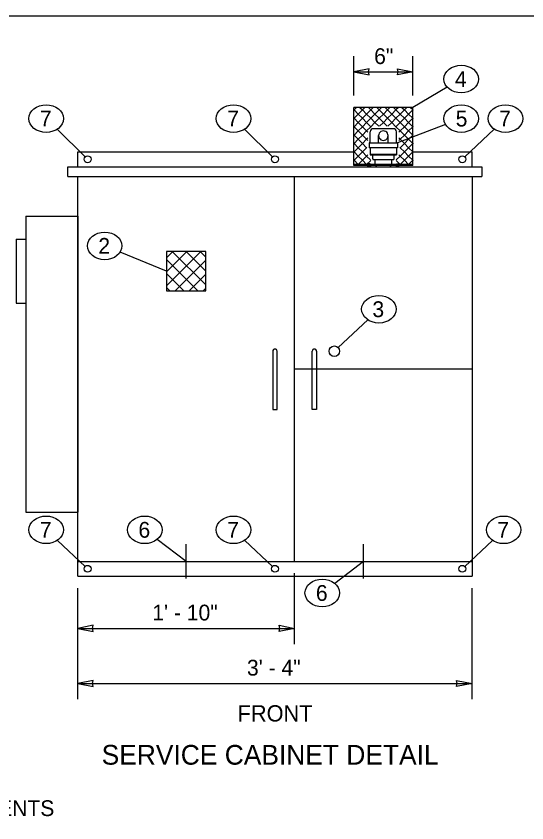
# Model space of a CAD drawing. Extents: x 99862 to 103680, y 99470 to 105076.
# Drawn here: x 100524 to 101043, y 101258 to 102076 of the extents above; entities that cross this region are included whole.
import ezdxf

# ---------------------------------------------------------------- set-up
doc = ezdxf.new("R2010")
doc.units = 0
for name, color, linetype in [('Level 1', 7, 'Continuous'), ('Level 15', 7, 'Continuous'), ('Level 20', 7, 'Continuous'), ('Level 35', 7, 'Continuous'), ('Level 40', 7, 'Continuous')]:
    doc.layers.add(name, color=color, linetype=linetype)

msp = doc.modelspace()

# ---------------------------------------------------------------- linework, layer by layer
at = {"layer": 'Level 1'}
for p, q in [((100866.96, 101925.19), (100866.96, 101982.94)), ((100926.96, 101982.94), (100866.96, 101982.94)), ((100866.96, 101980.71), (100867.18, 101980.49)), ((100867.18, 101980.49), (100866.96, 101980.27)), ((100867.18, 101980.49), (100869.64, 101982.94)), ((100871.44, 101976.24), (100867.18, 101980.49)), ((100875.69, 101980.49), (100871.44, 101976.24)), ((100873.24, 101982.94), (100875.69, 101980.49)), ((100878.14, 101982.94), (100875.69, 101980.49)), ((100875.69, 101980.49), (100879.95, 101976.24)), ((100879.95, 101976.24), (100884.2, 101980.49)), ((100884.2, 101980.49), (100881.75, 101982.94)), ((100886.65, 101982.94), (100884.2, 101980.49)), ((100884.2, 101980.49), (100888.45, 101976.24)), ((100888.45, 101976.24), (100892.71, 101980.49)), ((100892.71, 101980.49), (100890.26, 101982.94)), ((100895.16, 101982.94), (100892.71, 101980.49)), ((100892.71, 101980.49), (100896.96, 101976.24)), ((100896.96, 101976.24), (100901.22, 101980.49)), ((100901.22, 101980.49), (100898.76, 101982.94)), ((100903.67, 101982.94), (100901.22, 101980.49)), ((100901.22, 101980.49), (100905.47, 101976.24)), ((100905.47, 101976.24), (100909.73, 101980.49)), ((100909.73, 101980.49), (100907.27, 101982.94)), ((100912.18, 101982.94), (100909.73, 101980.49)), ((100909.73, 101980.49), (100913.98, 101976.24)), ((100913.98, 101976.24), (100918.23, 101980.49)), ((100915.78, 101982.94), (100918.23, 101980.49)), ((100918.23, 101980.49), (100920.69, 101982.94)), ((100918.23, 101980.49), (100922.49, 101976.24)), ((100922.49, 101976.24), (100926.74, 101980.49)), ((100926.74, 101980.49), (100924.29, 101982.94)), ((100926.96, 101980.71), (100926.74, 101980.49)), ((100926.74, 101980.49), (100926.96, 101980.27)), ((100926.96, 101925.19), (100926.96, 101982.95)), ((100866.96, 101972.21), (100867.18, 101971.98)), ((100867.18, 101971.98), (100866.96, 101971.76)), ((100867.18, 101971.98), (100871.44, 101976.24)), ((100871.44, 101967.73), (100867.18, 101971.98)), ((100871.44, 101976.24), (100875.69, 101971.98)), ((100875.69, 101971.98), (100871.44, 101967.73)), ((100879.95, 101976.24), (100875.69, 101971.98)), ((100875.69, 101971.98), (100879.95, 101967.73)), ((100884.2, 101971.98), (100879.95, 101976.24)), ((100879.95, 101967.73), (100884.2, 101971.98)), ((100888.45, 101976.24), (100884.2, 101971.98)), ((100884.2, 101971.98), (100888.45, 101967.73)), ((100892.71, 101971.98), (100888.45, 101976.24)), ((100888.45, 101967.73), (100892.71, 101971.98)), ((100896.96, 101976.24), (100892.71, 101971.98)), ((100892.71, 101971.98), (100896.96, 101967.73)), ((100901.22, 101971.98), (100896.96, 101976.24)), ((100896.96, 101967.73), (100901.22, 101971.98)), ((100905.47, 101976.24), (100901.22, 101971.98)), ((100901.22, 101971.98), (100905.47, 101967.73)), ((100909.73, 101971.98), (100905.47, 101976.24)), ((100905.47, 101967.73), (100909.73, 101971.98)), ((100913.98, 101976.24), (100909.73, 101971.98)), ((100909.73, 101971.98), (100913.98, 101967.73)), ((100918.23, 101971.98), (100913.98, 101976.24)), ((100913.98, 101967.73), (100918.23, 101971.98)), ((100922.49, 101976.24), (100918.23, 101971.98)), ((100918.23, 101971.98), (100922.49, 101967.73)), ((100926.74, 101971.98), (100922.49, 101976.24)), ((100922.49, 101967.73), (100926.74, 101971.98)), ((100926.96, 101972.2), (100926.74, 101971.98)), ((100926.74, 101971.98), (100926.96, 101971.76)), ((100866.96, 101963.7), (100867.18, 101963.48)), ((100867.18, 101963.48), (100866.96, 101963.25)), ((100867.18, 101963.48), (100871.44, 101967.73)), ((100871.44, 101959.22), (100867.18, 101963.48)), ((100871.44, 101967.73), (100875.69, 101963.48)), ((100875.69, 101963.48), (100871.44, 101959.22)), ((100879.95, 101967.73), (100875.69, 101963.48)), ((100875.69, 101963.48), (100879.95, 101959.22)), ((100884.2, 101963.48), (100879.95, 101967.73)), ((100879.95, 101959.22), (100884.2, 101963.48)), ((100888.45, 101967.73), (100884.2, 101963.48)), ((100884.2, 101963.48), (100884.42, 101963.26)), ((100892.33, 101963.86), (100888.45, 101967.73)), ((100896.96, 101967.73), (100893.09, 101963.86)), ((100900.84, 101963.86), (100896.96, 101967.73)), ((100905.47, 101967.73), (100901.6, 101963.86)), ((100909.73, 101963.48), (100905.47, 101967.73)), ((100909.51, 101963.26), (100909.73, 101963.48)), ((100913.98, 101967.73), (100909.73, 101963.48)), ((100909.73, 101963.48), (100913.98, 101959.22)), ((100918.23, 101963.48), (100913.98, 101967.73)), ((100913.98, 101959.22), (100918.23, 101963.48)), ((100922.49, 101967.73), (100918.23, 101963.48)), ((100918.23, 101963.48), (100922.49, 101959.22)), ((100926.74, 101963.48), (100922.49, 101967.73)), ((100922.49, 101959.22), (100926.74, 101963.48)), ((100926.96, 101963.7), (100926.74, 101963.48)), ((100926.74, 101963.48), (100926.96, 101963.26)), ((100866.96, 101955.19), (100867.18, 101954.97)), ((100867.18, 101954.97), (100866.96, 101954.75)), ((100867.18, 101954.97), (100871.44, 101959.22)), ((100871.44, 101950.71), (100867.18, 101954.97)), ((100871.44, 101959.22), (100875.69, 101954.97)), ((100875.69, 101954.97), (100871.44, 101950.71)), ((100879.95, 101959.22), (100875.69, 101954.97)), ((100875.69, 101954.97), (100879.95, 101950.71)), ((100881.32, 101957.85), (100879.95, 101959.22)), ((100883.73, 101947.01), (100883.73, 101958.24)), ((100906.99, 101961.45), (100886.94, 101961.45)), ((100892.15, 101947.01), (100892.15, 101954.39)), ((100901.78, 101947.01), (100901.78, 101954.39)), ((100910.2, 101947.01), (100910.2, 101958.24)), ((100913.98, 101959.22), (100912.6, 101957.85)), ((100918.23, 101954.97), (100913.98, 101959.22)), ((100913.98, 101950.71), (100918.23, 101954.97)), ((100922.49, 101959.22), (100918.23, 101954.97)), ((100918.23, 101954.97), (100922.49, 101950.71)), ((100926.74, 101954.97), (100922.49, 101959.22)), ((100922.49, 101950.71), (100926.74, 101954.97)), ((100926.96, 101955.19), (100926.74, 101954.97)), ((100926.74, 101954.97), (100926.96, 101954.75)), ((100866.96, 101946.68), (100867.18, 101946.46)), ((100867.18, 101946.46), (100866.96, 101946.24)), ((100867.18, 101946.46), (100871.44, 101950.71)), ((100871.44, 101942.2), (100867.18, 101946.46)), ((100871.44, 101950.71), (100875.69, 101946.46)), ((100875.69, 101946.46), (100871.44, 101942.2)), ((100879.95, 101950.71), (100875.69, 101946.46)), ((100875.69, 101946.46), (100879.95, 101942.2)), ((100879.95, 101950.71), (100881.32, 101952.09)), ((100881.24, 101949.42), (100879.95, 101950.71)), ((100883.73, 101947.01), (100882.52, 101947.01)), ((100882.52, 101947.01), (100882.52, 101942.2)), ((100883.73, 101947.01), (100910.2, 101947.01)), ((100910.2, 101947.01), (100911.4, 101947.01)), ((100911.4, 101947.01), (100911.4, 101942.2)), ((100912.6, 101952.09), (100913.98, 101950.71)), ((100913.98, 101950.71), (100912.68, 101949.42)), ((100918.23, 101946.46), (100913.98, 101950.71)), ((100913.98, 101942.2), (100918.23, 101946.46)), ((100922.49, 101950.71), (100918.23, 101946.46)), ((100918.23, 101946.46), (100922.49, 101942.2)), ((100926.74, 101946.46), (100922.49, 101950.71)), ((100922.49, 101942.2), (100926.74, 101946.46)), ((100926.96, 101946.68), (100926.74, 101946.46)), ((100926.74, 101946.46), (100926.96, 101946.24)), ((100866.96, 101938.17), (100867.18, 101937.95)), ((100867.18, 101937.95), (100866.96, 101937.73)), ((100867.18, 101937.95), (100871.44, 101942.2)), ((100871.44, 101933.7), (100867.18, 101937.95)), ((100871.44, 101942.2), (100875.69, 101937.95)), ((100875.69, 101937.95), (100871.44, 101933.7)), ((100879.95, 101942.2), (100875.69, 101937.95)), ((100875.69, 101937.95), (100879.95, 101933.7)), ((100879.95, 101942.2), (100880.12, 101942.38)), ((100880.12, 101942.03), (100879.95, 101942.2)), ((100911.4, 101942.2), (100882.52, 101942.2)), ((100883.73, 101942.2), (100883.73, 101934.98)), ((100910.2, 101942.2), (100910.2, 101934.98)), ((100913.81, 101942.38), (100913.98, 101942.2)), ((100913.98, 101942.2), (100913.81, 101942.03)), ((100918.23, 101937.95), (100913.98, 101942.2)), ((100913.98, 101933.7), (100918.23, 101937.95)), ((100922.49, 101942.2), (100918.23, 101937.95)), ((100918.23, 101937.95), (100922.49, 101933.7)), ((100926.74, 101937.95), (100922.49, 101942.2)), ((100922.49, 101933.7), (100926.74, 101937.95)), ((100926.96, 101938.17), (100926.74, 101937.95)), ((100926.74, 101937.95), (100926.96, 101937.73)), ((100866.96, 101929.66), (100867.18, 101929.44)), ((100867.18, 101929.44), (100871.44, 101933.7)), ((100871.44, 101933.7), (100875.69, 101929.44)), ((100879.95, 101933.7), (100875.69, 101929.44)), ((100879.95, 101933.7), (100881.32, 101935.07)), ((100883.91, 101929.73), (100879.95, 101933.7)), ((100883.73, 101935.58), (100910.2, 101935.58)), ((100883.73, 101934.98), (100910.2, 101934.98)), ((100886.13, 101930.77), (100886.13, 101934.98)), ((100886.73, 101930.16), (100907.19, 101930.16)), ((100888.54, 101925.35), (100888.54, 101930.16)), ((100905.39, 101925.35), (100905.39, 101930.16)), ((100907.79, 101930.77), (100907.79, 101934.98)), ((100913.98, 101933.7), (100910.01, 101929.73)), ((100912.6, 101935.07), (100913.98, 101933.7)), ((100918.23, 101929.44), (100913.98, 101933.7)), ((100922.49, 101933.7), (100918.23, 101929.44)), ((100926.74, 101929.44), (100922.49, 101933.7)), ((100926.96, 101929.66), (100926.74, 101929.44)), ((100867.18, 101929.44), (100866.96, 101929.22)), ((100926.96, 101925.19), (100866.96, 101925.19)), ((100866.96, 101924.15), (100866.96, 101925.09)), ((100926.96, 101925.09), (100866.96, 101925.09)), ((100926.96, 101924.15), (100866.96, 101924.15)), ((100871.44, 101925.19), (100867.18, 101929.44)), ((100875.69, 101929.44), (100871.44, 101925.19)), ((100875.69, 101929.44), (100879.95, 101925.19)), ((100879.95, 101925.19), (100884.09, 101929.33)), ((100890.95, 101922.94), (100902.98, 101922.94)), ((100909.83, 101929.33), (100913.98, 101925.19)), ((100913.98, 101925.19), (100918.23, 101929.44)), ((100918.23, 101929.44), (100922.49, 101925.19)), ((100922.49, 101925.19), (100926.74, 101929.44)), ((100926.74, 101929.44), (100926.96, 101929.22)), ((100926.96, 101924.15), (100926.96, 101925.09)), ((100534.46, 101872.94), (100586.96, 101872.94)), ((100534.46, 101872.94), (100534.46, 101572.94)), ((100586.96, 101872.94), (100586.96, 101572.94)), ((100524.46, 101849.63), (100534.46, 101849.63)), ((100524.46, 101849.63), (100524.46, 101784.63)), ((100524.46, 101784.63), (100534.46, 101784.63)), ((100784.75, 101735.95), (100784.75, 101732.99)), ((100789.18, 101732.99), (100789.18, 101735.95)), ((100824.75, 101732.99), (100824.75, 101735.95)), ((100829.18, 101735.95), (100829.18, 101732.99)), ((100784.75, 101732.99), (100784.75, 101676.86)), ((100789.18, 101676.86), (100789.18, 101732.99)), ((100824.75, 101676.86), (100824.75, 101732.99)), ((100829.18, 101732.99), (100829.18, 101676.86)), ((100784.75, 101676.86), (100789.18, 101676.86)), ((100829.18, 101676.86), (100824.75, 101676.86)), ((100534.46, 101572.94), (100586.96, 101572.94))]:
    msp.add_line(p, q, dxfattribs=at)
msp.add_lwpolyline([(99862, 99999.5), (103151, 99999.5), (103151, 102075.5), (99862, 102075.5)], close=True, dxfattribs=at)
msp.add_circle((100847.27, 101735.95), 5.34, dxfattribs=at)
for centre, radius, start, end in [((100886.94, 101958.24), 3.21, 90, 180), ((100896.96, 101954.39), 4.81, 359.99971, 180), ((100896.96, 101954.39), 4.81, 180, 0.00029), ((100906.99, 101958.24), 3.21, 0, 90), ((100886.73, 101930.77), 0.602, 180, 270), ((100907.19, 101930.77), 0.602, 270, 0), ((100890.95, 101925.35), 2.41, 180, 270), ((100902.98, 101925.35), 2.41, 270, 0), ((100786.96, 101735.95), 2.22, 0, 180), ((100826.96, 101735.95), 2.22, 0, 180)]:
    msp.add_arc(centre, radius, start, end, dxfattribs=at)
at = {"layer": 'Level 15'}
for p, q in [((100866.96, 101994.94), (100866.96, 102034.94)), ((100926.96, 101994.94), (100926.96, 102034.94)), ((100866.96, 102018.94), (100926.96, 102018.94)), ((100961.82, 102003.41), (100926.96, 101982.94)), ((100960.14, 101965.65), (100911.4, 101947.01)), ((100594.47, 101932.9), (100566.01, 101960.84)), ((100784.47, 101932.9), (100756.01, 101960.84)), ((100979.51, 101932.84), (101009.48, 101961.03)), ((100576.96, 101922.94), (100996.96, 101922.94)), ((100576.96, 101912.94), (100576.96, 101922.94)), ((100996.96, 101922.94), (100996.96, 101912.94)), ((100576.96, 101912.94), (100996.96, 101912.94)), ((100676.96, 101817.13), (100629.9, 101836.33)), ((100851.12, 101739.65), (100881.09, 101767.83)), ((100594.41, 101517.84), (100566.3, 101544.28)), ((100696.96, 101522.94), (100667.63, 101545.29)), ((100696.96, 101505.44), (100696.96, 101540.44)), ((100784.41, 101517.84), (100756.3, 101544.28)), ((100876.96, 101505.44), (100876.96, 101540.44)), ((100979.51, 101517.84), (101007.62, 101544.28)), ((100876.96, 101522.94), (100847.63, 101500.6)), ((100806.96, 101439.08), (100806.96, 101510.94)), ((100586.96, 101383.22), (100586.96, 101495.94)), ((100986.96, 101383.22), (100986.96, 101495.94)), ((100586.96, 101455.08), (100806.96, 101455.08)), ((100586.96, 101399.22), (100986.96, 101399.22))]:
    msp.add_line(p, q, dxfattribs=at)
for points in [[(100866.96, 102018.94), (100882.69, 102015.86), (100881.96, 102018.94), (100882.69, 102022.03)], [(100926.96, 102018.94), (100911.24, 102015.86), (100911.97, 102018.94), (100911.24, 102022.03)], [(100586.96, 101455.08), (100602.69, 101452), (100601.96, 101455.08), (100602.69, 101458.17)], [(100806.96, 101455.08), (100791.24, 101452), (100791.97, 101455.08), (100791.24, 101458.17)], [(100586.96, 101399.22), (100602.69, 101396.14), (100601.96, 101399.22), (100602.69, 101402.31)], [(100986.96, 101399.22), (100971.24, 101396.14), (100971.97, 101399.22), (100971.24, 101402.31)]]:
    msp.add_lwpolyline(points, close=True, dxfattribs=at)
for centre in [(100596.96, 101930.44), (100786.96, 101930.44), (100976.96, 101930.44), (100596.96, 101515.44), (100786.96, 101515.44), (100976.96, 101515.44)]:
    msp.add_circle(centre, 3.5, dxfattribs=at)
at = {"layer": 'Level 20'}
for centre, major_axis in [((100975.93, 102011.69), (-17.5, 0)), ((100554.96, 101971.69), (-17.5, 0)), ((100744.96, 101971.69), (-17.5, 0)), ((100975.93, 101971.69), (-17.5, 0)), ((101020.82, 101971.69), (-17.5, 0)), ((100614.31, 101842.68), (-17.5, 0)), ((100892.43, 101778.5), (-17.5, 0)), ((100554.96, 101554.94), (-17.5, 0)), ((100654.96, 101554.94), (-17.5, 0)), ((100744.96, 101554.94), (-17.5, 0)), ((101018.96, 101554.94), (-17.5, 0)), ((100834.96, 101490.94), (17.5, 0))]:
    msp.add_ellipse(centre, major_axis=major_axis, ratio=0.8, dxfattribs=at)
at = {"layer": 'Level 35'}
msp.add_line((100806.96, 101717.94), (100986.96, 101717.94), dxfattribs=at)
at = {"layer": 'Level 40'}
for p, q in [((100586.96, 101937.94), (100866.96, 101937.94)), ((100586.96, 101922.94), (100586.96, 101937.94)), ((100926.96, 101937.94), (100986.96, 101937.94)), ((100986.96, 101922.94), (100986.96, 101937.94)), ((100586.96, 101922.94), (100986.96, 101922.94)), ((100586.96, 101507.94), (100586.96, 101912.94)), ((100806.96, 101522.94), (100806.96, 101912.94)), ((100986.96, 101912.94), (100986.96, 101507.94)), ((100676.96, 101802.33), (100711.76, 101837.13)), ((100676.96, 101816.47), (100697.62, 101837.13)), ((100676.96, 101830.62), (100683.47, 101837.13)), ((100682.89, 101837.13), (100716.96, 101803.06)), ((100697.03, 101837.13), (100716.96, 101817.2)), ((100711.17, 101837.13), (100716.96, 101831.34)), ((100676.96, 101828.91), (100708.75, 101797.13)), ((100685.9, 101797.13), (100716.96, 101828.19)), ((100676.96, 101814.77), (100694.61, 101797.13)), ((100700.04, 101797.13), (100716.96, 101814.05)), ((100676.96, 101800.63), (100680.46, 101797.13)), ((100714.19, 101797.13), (100716.96, 101799.91)), ((100586.96, 101522.94), (100986.96, 101522.94)), ((100586.96, 101507.94), (100986.96, 101507.94))]:
    msp.add_line(p, q, dxfattribs=at)
for points in [[(100883.87, 101923.19), (100883.87, 101922.94), (100881.18, 101922.94), (100881.18, 101923.19)], [(100883.84, 101923.35), (100883.84, 101923.19), (100881.21, 101923.19), (100881.21, 101923.35)], [(100883.51, 101925.11), (100883.51, 101925.88), (100881.54, 101925.88), (100881.54, 101925.11)], [(100883.51, 101923.35), (100883.51, 101924.15), (100881.54, 101924.15), (100881.54, 101923.35)], [(100910.06, 101923.19), (100910.06, 101922.94), (100912.74, 101922.94), (100912.74, 101923.19)], [(100910.09, 101923.35), (100910.09, 101923.19), (100912.72, 101923.19), (100912.72, 101923.35)], [(100910.42, 101925.11), (100910.42, 101925.88), (100912.39, 101925.88), (100912.39, 101925.11)], [(100910.42, 101923.35), (100910.42, 101924.15), (100912.39, 101924.15), (100912.39, 101923.35)], [(100676.96, 101797.13), (100716.96, 101797.13), (100716.96, 101837.13), (100676.96, 101837.13)]]:
    msp.add_lwpolyline(points, close=True, dxfattribs=at)

# ---------------------------------------------------------------- texts
at = {"layer": 'Level 20'}
for s, p in [('6"', (100887.6, 102026.94)), ('1\' - 10"', (100662.58, 101463.08)), ('3\' - 4"', (100758.63, 101407.22)), ('METER SOCKET/BASE PANEL PER UTILITY REQUIREMENTS', (99941.45, 101264.85))]:
    msp.add_text(s, height=16, rotation=360, dxfattribs=at).set_placement(p)
for s, height, p in [('4', 16, (100969.49, 102003.69)), ('7', 16, (100548.53, 101963.69)), ('7', 16, (100738.53, 101963.69)), ('5', 16, (100970.34, 101963.69)), ('7', 16, (101014.39, 101963.69)), ('2', 16, (100607.86, 101834.68)), ('3', 16, (100885.85, 101770.5)), ('7', 16, (100548.53, 101546.94)), ('6', 16, (100648.53, 101546.94)), ('7', 16, (100738.53, 101546.94)), ('7', 16, (101012.53, 101546.94)), ('6', 16, (100828.53, 101482.94)), ('FRONT', 16.5, (100749.14, 101360.69)), ('SERVICE CABINET DETAIL', 20, (100611.21, 101316.94))]:
    msp.add_text(s, height=height, dxfattribs=at).set_placement(p)

doc.saveas('drawing.dxf')
